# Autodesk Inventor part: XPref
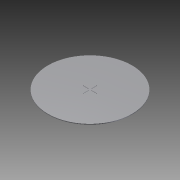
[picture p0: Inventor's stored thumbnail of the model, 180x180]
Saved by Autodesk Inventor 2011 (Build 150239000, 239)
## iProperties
Created: 2014-11
Part Number: XPref
Document SubType Name: Modeling
Designer: Evgeny
Density: 1 g/cm^3
Author: Evgeny
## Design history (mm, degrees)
sketch "Эскиз1"
  geometry: L1 (2, 0.25)-(10, 0.25); L2 (10, 0.25)-(10, -0.25); L3 (2, -0.25)-(2, 0.25); L4 (0.25, 2)-(-0.25, 2); L5 (-0.25, 2)-(-0.25, 10); L6 (-0.25, 10)-(0.25, 10); L7 (0.25, 10)-(0.25, 2); L8 (-2, 0.25)-(-10, 0.25); L9 (-10, 0.25)-(-10, -0.25); L10 (-10, -0.25)-(-2, -0.25); L11 (-2, -0.25)-(-2, 0.25); L12 (0.25, -2)-(0.25, -10); L13 (0.25, -10)-(-0.25, -10); L14 (-0.25, -10)-(-0.25, -2); L15 (2, -0.25)-(10, -0.25); L16 (-0.25, -2)-(0.25, -2); C1 r 60 at (0, 0); 1 further point
  constraints: 32 end point, 6 parallel, 5 perpendicular, 4 collinear, 3 horizontal, 1 centre point, 1 coincident
  dimensions: "d27" = 120 diameter of C1; "d33" = 2 distance from line of L4 point (0, 0); "d35" = 2 distance from line of L11 point (0, 0); "d36" = 4 distance between parallel lines of L3 L11; "d37" = 0.5 distance between parallel lines of L7 L5; "d38" = 0.25 distance from line of L5 point (0, 0); "d39" = 0.5 distance between parallel lines of L10 L8; "d40" = 0.25 distance from line of point (0, 0) L10; "d41" = 4 distance between parallel lines of L16 L4; "d42" = 8 distance between parallel lines of L9 L11; "d43" = 8 distance between parallel lines of L6 L4; "d44" = 8 distance between parallel lines of L2 L3; "d45" = 8 distance between parallel lines of L13 L16
extrude "Выдавливание3" new body sketch "Эскиз1" distance "d46" = 1; taper "d47" = 0 deg
node "Твердое тело3"
